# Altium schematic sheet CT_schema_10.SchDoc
size 391 x 238 mm
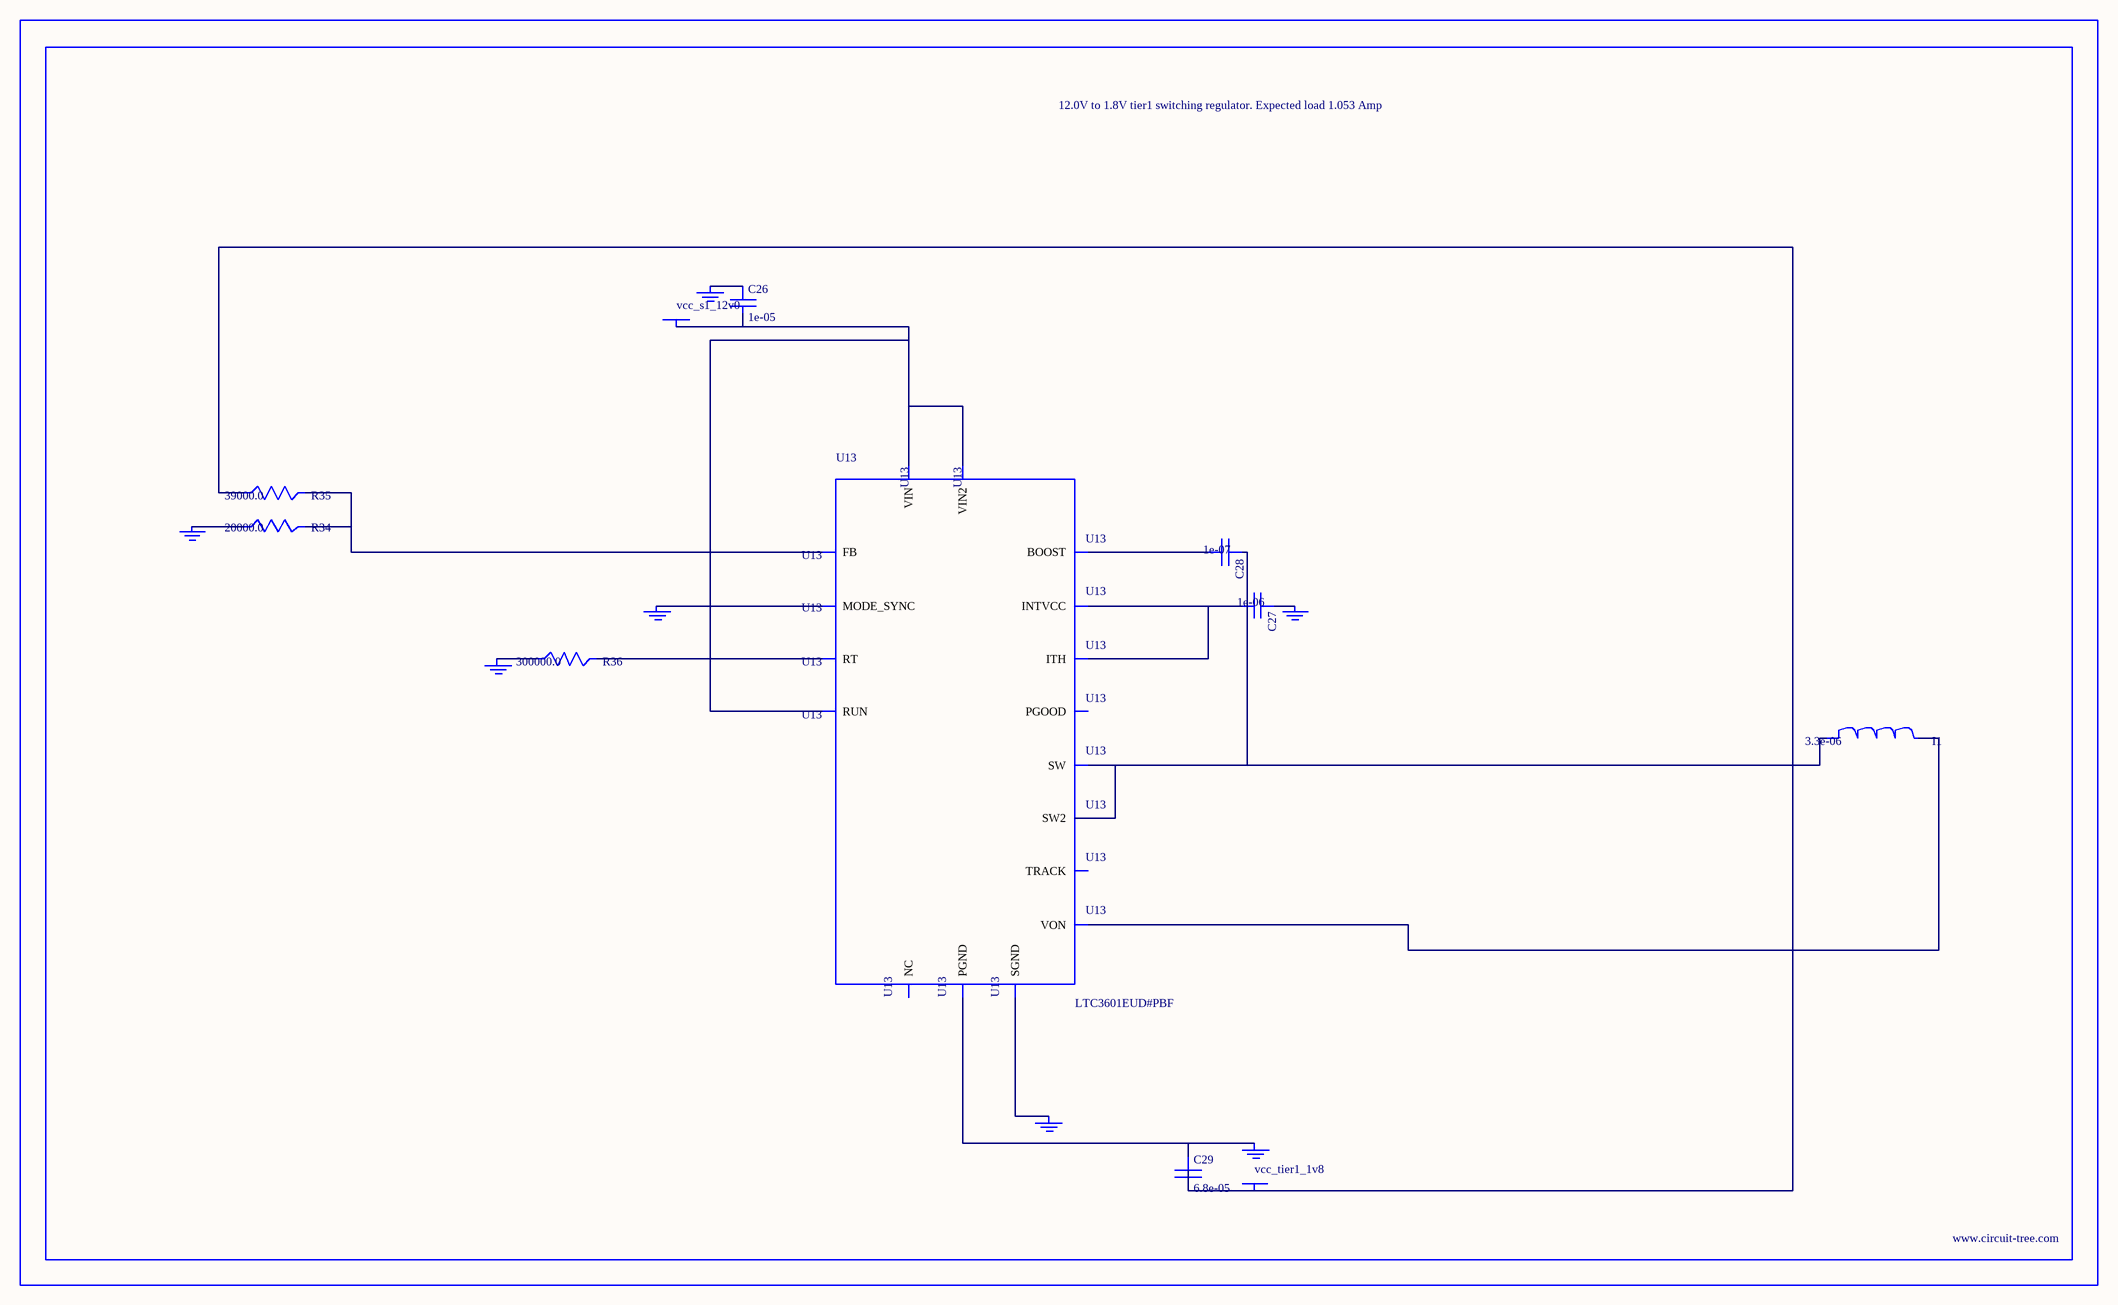
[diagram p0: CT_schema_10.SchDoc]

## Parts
BORDER9  (no value)
C26  1e-05  [C0805]
C27  1e-06  [C0603]
C28  1e-07  [C0402]
C29  6.8e-05  [2220]
GND_INSTANCE_9_0  (no value)
GND_INSTANCE_9_1  (no value)
GND_INSTANCE_9_2  (no value)
GND_INSTANCE_9_3  (no value)
GND_INSTANCE_9_4  (no value)
GND_INSTANCE_9_5  (no value)
GND_INSTANCE_9_6  (no value)
I1  3.3e-06  [WE-HCI_7030/7040/7050]
POWER_INSTANCE_9_0  vcc_s1_12v0
POWER_INSTANCE_9_1  vcc_tier1_1v8
R34  20000.0  [R0603]
R35  39000.0  [R0603]
R36  300000.0  [R0603]
U13  LTC3601EUD#PBF  [QFN-16_EP]

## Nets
NetC26_1: C26.1 GND_INSTANCE_9_5.0(GND)
NetC26_2: C26.2 POWER_INSTANCE_9_0.0(PWR) U13.14(RUN) U13.15(VIN) U13.16(VIN2)
NetC27_1: C27.1 GND_INSTANCE_9_1.0(GND)
NetC27_2: C27.2 U13.7(INTVCC) U13.12(ITH)
NetC28_1: C28.1 I1.1 U13.3(SW) U13.4(SW2)
NetC28_2: C28.2 U13.6(BOOST)
NetC29_1: C29.1 GND_INSTANCE_9_6.0(GND) U13.17(PGND)
NetC29_2: C29.2 I1.2 POWER_INSTANCE_9_1.0(PWR) R35.1 U13.8(VON)
NetGND_INSTANCE_9_0_0: GND_INSTANCE_9_0.0(GND) U13.1(MODE_SYNC)
NetGND_INSTANCE_9_2_0: GND_INSTANCE_9_2.0(GND) U13.9(SGND)
NetGND_INSTANCE_9_3_0: GND_INSTANCE_9_3.0(GND) R36.1
NetGND_INSTANCE_9_4_0: GND_INSTANCE_9_4.0(GND) R34.1
NetR34_2: R34.2 R35.2 U13.11(FB)
NetR36_2: R36.2 U13.10(RT)

Not connected (* = marked no-connect by the designer): U13 2(PGOOD) 5(NC) 13(TRACK)

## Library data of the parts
BORDER9 = BORDER_PAGE9
C26 = C0805C106K8RACTU
C27 = C0603C105K3RACTU
C28 = C0402C104K3RACTU
C29 = C5750X5R1A686M
GND_INSTANCE_9_0-GND_INSTANCE_9_6 = GND
I1 = 744314330
POWER_INSTANCE_9_0 POWER_INSTANCE_9_1 = PWR
R34 = RC0603JR-0720KL
R35 = RC0603JR-0739KL
R36 = RC0603JR-07300KL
